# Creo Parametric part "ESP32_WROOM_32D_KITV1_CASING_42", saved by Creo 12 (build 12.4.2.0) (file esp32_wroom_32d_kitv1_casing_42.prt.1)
Units: Custom; MM, KILOGRAM, SECS

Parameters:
  PTC_WM_ITERATION = "0"
  PTC_WM_VERSION = "-.0"
  PTC_WM_LIFECYCLE_STATE = "In Work"
  PTC_WM_LIFECYCLE = "MO_CADDocument"
  PTC_WM_CREATED_BY = "Maximilian Roepper (Z0017RMS: MO)"
  PTC_WM_CREATED_ON = "18-Sep-26 11:36:42 AM"
  PTC_WM_MODIFIED_BY = "Maximilian Roepper (Z0017RMS: MO)"
  PTC_WM_MODIFIED_ON = "18-Sep-26 11:36:46 AM"
  PDMLINKNUMBER = "PDM000071455232"
  PTC_WM_NAME = "esp32_wroom_32d_kitv1_casing_42.prt"
  PTC_WM_NUMBER = "PDM000071455232"

Other parameters: WEIGHT, WEIGHT_FACTOR, WEIGHT_ADD, _MASS_TEMP, _DIFF_TEMP, MC_ERRORS, SUPPLIER

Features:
  1. coordinate system
  2. datum plane "PRT_YZ"
  3. datum plane "PRT_XY"
  4. datum plane "PRT_XZ"
  5. coordinate system
  6. datum axis
  7. datum axis
  8. datum axis
  9. coordinate system
  10. imported feature
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
Other named items: PRT, SIEMENS_MO, DRW_VIEW_ORG, PRT_X, PRT_Y, PRT_Z, CS0, ROUGH_GROB

Layers: 00_STD_CSYS-KSYS, 01_STD_PLANES-EBENEN, 02_STD_AXES-ACHSEN, 03_STD_CSYS-KSYS, 24_IMPORT_FEAT-IMPORT_KE

Surfaces: 5 plane, 1 cylinder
